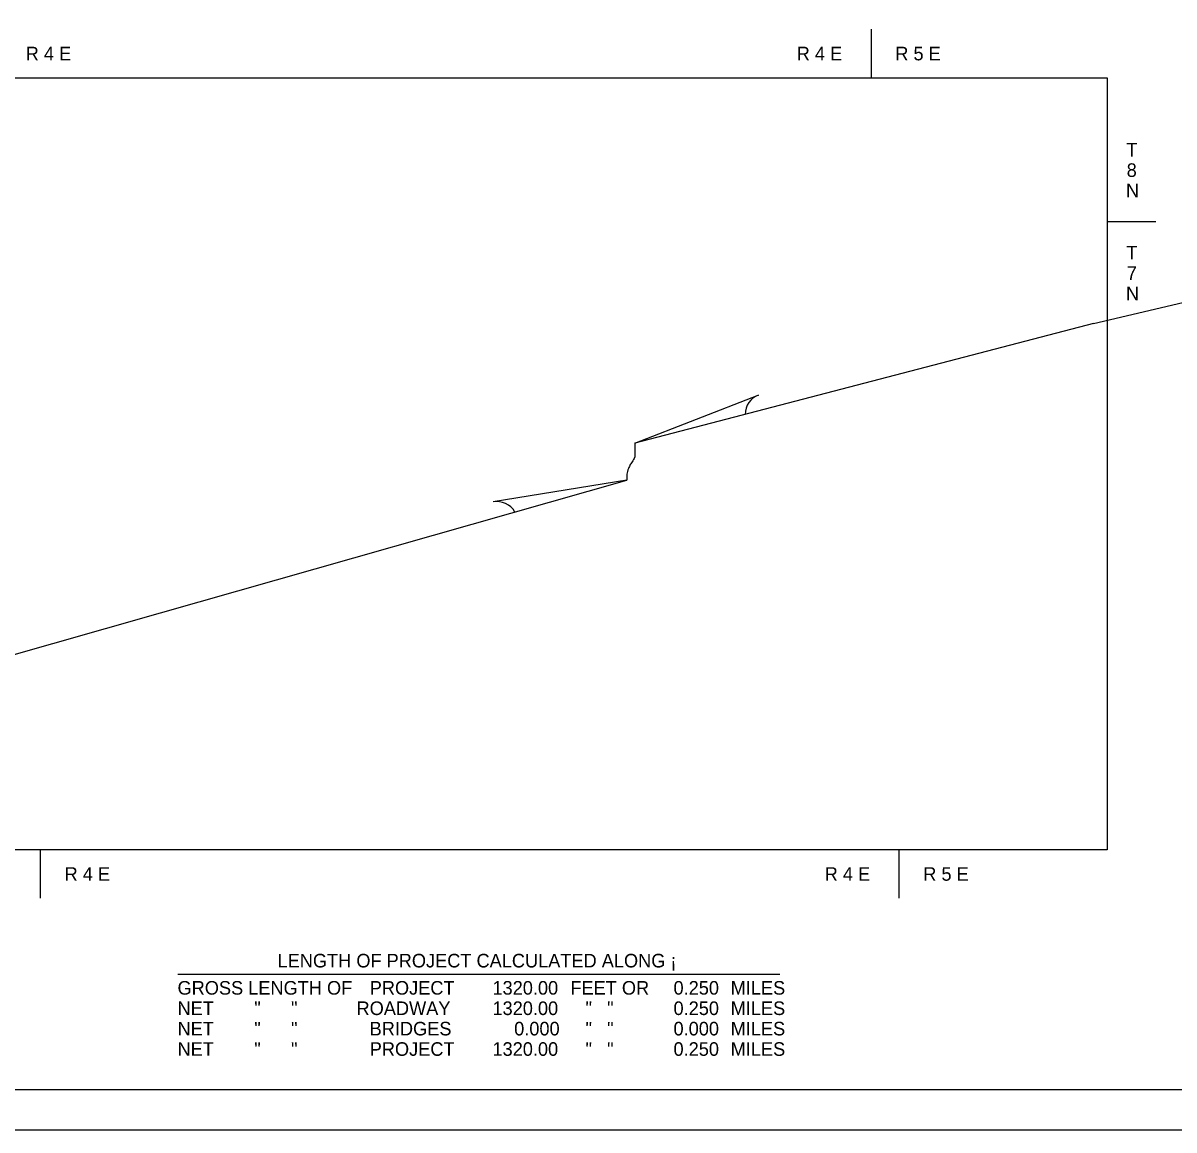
# Model space of a CAD drawing. Extents: x -0.68 to 1.92, y 0 to 0.95.
# Drawn here: x 0.474 to 1.066, y 0 to 0.57 of the extents above; entities that cross this region are included whole.
import ezdxf

# ---------------------------------------------------------------- set-up
doc = ezdxf.new("R2010")
doc.units = 0
for name, color, linetype in [('Default', 7, 'Continuous'), ('DSN_DRFT_DNC', 7, 'Continuous'), ('DSN_DRFT_Guideline-No-Plot', 7, 'Continuous'), ('SHET_Annotations', 7, 'Continuous'), ('SHET_Border-Lines', 7, 'Continuous'), ('SHET_Border-Text', 7, 'Continuous')]:
    doc.layers.add(name, color=color, linetype=linetype)

msp = doc.modelspace()

# ---------------------------------------------------------------- linework, layer by layer
at = {"layer": 'Default'}
for p, q in [((1.02482, 0.41518), (1.21127, 0.45932)), ((0.85226, 0.37831), (0.85234, 0.37831)), ((0.71575, 0.32337), (0.71568, 0.32333)), ((0.31471, 0.20092), (0.54446, 0.26626))]:
    msp.add_line(p, q, dxfattribs=at)
for points in [[(1.02482, 0.41518), (0.78873, 0.35358), (0.85226, 0.37831)], [(0.54446, 0.26626), (0.7846, 0.33456), (0.71575, 0.32337)]]:
    msp.add_lwpolyline(points, dxfattribs=at)
for centre, radius, start, end in [((0.85584, 0.36857), 0.01035, 109.74289, 180.99653), ((0.71766, 0.31293), 0.01059, 29.50362, 100.75726)]:
    msp.add_arc(centre, radius, start, end, dxfattribs=at)
msp.add_spline([(0.78873, 0.35358), (0.78873, 0.34962), (0.7883, 0.34569), (0.78689, 0.34346), (0.78586, 0.34162), (0.78539, 0.34048), (0.78459, 0.33764), (0.7846, 0.33456)], degree=3, dxfattribs=at)
at = {"layer": 'DSN_DRFT_DNC'}
msp.add_lwpolyline([(0.38477, 0.54167), (1.0319, 0.54167), (1.0319, 0.1443), (0.38477, 0.1443)], close=True, dxfattribs=at)
at = {"layer": 'DSN_DRFT_Guideline-No-Plot'}
msp.add_lwpolyline([(0, 0), (1.41667, 0), (1.41667, 0.91667), (0, 0.91667)], close=True, dxfattribs=at)
at = {"layer": 'SHET_Annotations'}
for p, q in [((0.91031, 0.56667), (0.91031, 0.54167)), ((1.0319, 0.46765), (1.0569, 0.46765)), ((0.48249, 0.1443), (0.48249, 0.1193)), ((0.9247, 0.1443), (0.9247, 0.1193))]:
    msp.add_line(p, q, dxfattribs=at)
at = {"layer": 'SHET_Border-Lines'}
msp.add_lwpolyline([(0.02083, 0.02083), (1.39583, 0.02083), (1.39583, 0.89583), (0.02083, 0.89583)], close=True, dxfattribs=at)
at = {"layer": 'SHET_Border-Text'}
msp.add_line((0.55333, 0.08017), (0.86333, 0.08017), dxfattribs=at)

# ---------------------------------------------------------------- texts
at = {"layer": 'SHET_Annotations'}
for s, p in [('R 4 E', (0.47497, 0.55067)), ('R 4 E', (0.87205, 0.55067)), ('R 5 E', (0.92281, 0.55067)), ('T', (1.04176, 0.50115)), ('8', (1.04196, 0.49065)), ('N', (1.0416, 0.48015)), ('T', (1.04176, 0.44815)), ('7', (1.04203, 0.43765)), ('N', (1.0416, 0.42715)), ('R 4 E', (0.49499, 0.1283)), ('R 4 E', (0.88644, 0.1283)), ('R 5 E', (0.9372, 0.1283)), ('1320.00', (0.71534, 0.06967)), ('0.250 ', (0.80858, 0.06967)), ('MILES', (0.83801, 0.06967)), ('1320.00', (0.71534, 0.05917)), ('0.250 ', (0.80858, 0.05917)), ('MILES', (0.83801, 0.05917)), ('0.000', (0.72652, 0.04867)), ('0.000 ', (0.80858, 0.04867)), ('MILES', (0.83801, 0.04867)), ('1320.00', (0.71534, 0.03817)), ('0.250 ', (0.80858, 0.03817)), ('MILES', (0.83801, 0.03817))]:
    msp.add_text(s, height=0.007, dxfattribs=at).set_placement(p)
at = {"layer": 'SHET_Border-Text'}
for s, p in [('LENGTH OF PROJECT CALCULATED ALONG ¡', (0.60467, 0.08367)), ('GROSS LENGTH OF', (0.55315, 0.06967)), ('PROJECT', (0.65213, 0.06967)), ('FEET OR', (0.75548, 0.06967)), ('NET        "      "', (0.55315, 0.05917)), ('ROADWAY', (0.64534, 0.05917)), ('   "   "', (0.75548, 0.05917)), ('NET        "      "', (0.55315, 0.04867)), ('BRIDGES', (0.65209, 0.04867)), ('   "   "', (0.75548, 0.04867)), ('NET        "      "', (0.55315, 0.03817)), ('PROJECT', (0.65213, 0.03817)), ('   "   "', (0.75548, 0.03817))]:
    msp.add_text(s, height=0.007, dxfattribs=at).set_placement(p)

doc.saveas('drawing.dxf')
